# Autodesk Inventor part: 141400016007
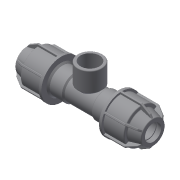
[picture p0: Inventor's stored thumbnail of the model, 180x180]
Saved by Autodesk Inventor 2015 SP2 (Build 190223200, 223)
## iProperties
Created: 2017-08
Part Number: 141400016007
Material: Generic
Description: PLASSON L.14 TEE FEMALE ADAPTOR (SILVER) 16 x 3/4" x 16
Document SubType Name: Modeling
Designer: KIM
Density: 1 g/cm^3
Appearance: Default
Author: KIM
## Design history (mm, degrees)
derived "141400.ipt"
feature "Solid1::141400.ipt"
feature "Solid2::141400.ipt"
tag "TaggingFeature1"
body "Solid1"
other parameters: "d1" = 16, "d4" = 15 deg, "d5" = 33, "d6" = 10.89, "d10" = 39, "d16" = 16.32, "d17" = 2.5, "d22" = 25.6, "d24" = 2.5, "d25" = 35.1, "d26" = 29.25, "d27" = 2.5, "d28" = 135 deg, "d29" = 1.5, "d31" = 0.8, "d46" = 150 deg, "d49" = 1.95, "d50" = 0, "d58" = 0.48, "d61" = 360 deg, "d63" = 14.4, "d64" = 61, "d80" = 23.04, "d81" = 1.28, "d84" = 2.5, "d95" = 24.117, "d96" = 31.3521, "d97" = 19, "d98" = 14.4, "d99" = 21.94647, "d100" = 135 deg, "d108" = 0.8, "d111" = 0, "d_" = 16, "G_" = 24.117, "E_" = 39, "H_" = 122, "l_2" = 19
